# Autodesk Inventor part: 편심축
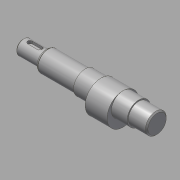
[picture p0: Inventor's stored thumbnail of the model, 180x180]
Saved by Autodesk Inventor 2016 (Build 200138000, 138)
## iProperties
Created: 2017-08
Part Number: 편심축
Material: 강철, 연강
Document SubType Name: Modeling
Designer: mduedu
Density: 1 g/cm^3
Appearance: 강철
Author: mduedu
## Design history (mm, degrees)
sketch "스케치1"
  geometry: L1 (0, 0)-(110, 0); L2 (110, 0)-(110, 8.5); L3 (110, 8.5)-(95, 8.5); L4 (95, 8.5)-(95, 9.5); L5 (95, 9.5)-(51, 9.5); L6 (51, 9.5)-(51, 8.5); L7 (51, 8.5)-(19, 8.5); L8 (19, 8.5)-(19, 6); L9 (19, 6)-(0, 6); L10 (0, 6)-(0, 0)
  constraints: 20 end point, 6 parallel, 2 collinear, 2 perpendicular, 1 horizontal
  dimensions: "d0" = 110 distance of L1.start L1.end; "d1" = 17 diameter of L3 L1; "d2" = 19 diameter of L5 L1; "d3" = 12 diameter of L9 L1; "d4" = 19 distance of L8.end L9.end; "d5" = 15 distance of L2.end L3.end; "d6" = 44 distance of L4.end L5.end
revolve "회전1" sketch "스케치1" stored, may be unused: angle "d7" = 90 deg
node "작업 평면1"
sketch "스케치2"
  geometry: C1 r 9.5 at (0, 0) reference; C2 r 13 at (0, -3.5); 1 further point
  constraints: 1 centre point, 1 tangent, 1 vertical alignment
  dimensions: "d8" = 3.5 distance of point (0, 0) C2.centre
extrude "돌출1" join sketch "스케치2" stored distance "d9" = 18; taper "d10" = 0 deg
chamfer "모따기1" distance "d11" = 1; stored, may be unused: second distance "d12" = 2, angle "d13" = 45 deg
node "작업 평면2"
sketch "스케치3"
  geometry: L1 (3.5, -2)-(-4.5, -2); L2 (-4.5, -2)-(-4.5, 2); L3 (-4.5, 2)-(3.5, 2); L4 (3.5, 2)-(3.5, -2); L5 (9.5, 6)-(9.5, -6) reference; A1 r 2 centre (3.5, 0) between (3.5, -2) and (3.5, 2); A2 r 2 centre (-4.5, 0) between (-4.5, 2) and (-4.5, -2); A3 r 2 centre (3.5, 0) between (3.5, 2) and (3.5, -2); A4 r 2 centre (-4.5, 0) between (-4.5, -2) and (-4.5, 2); 1 further point
  constraints: 8 end point, 8 point on circle, 4 centre point, 2 midpoint, 2 parallel, 1 horizontal, 1 horizontal alignment, 1 perpendicular
  dimensions: "d14" = 12 dimension on A2 A1; "d16" = 4 distance between parallel lines of L3 L1; "d17" = 4 distance edge to line of A1 L5
extrude "돌출2" cut sketch "스케치3" distance "d18" = 2.5; taper "d19" = 0 deg
chamfer "모따기2" distance "d20" = 1; stored, may be unused: second distance "d21" = 2, angle "d22" = 45 deg
chamfer "모따기3" distance "d23" = 1; stored, may be unused: second distance "d24" = 2, angle "d25" = 60 deg
fillet "모깎기1" dims "d26" = 0.5
hole "구멍1" diameter "d29" = 3.242; stored, may be unused: countersink angle "d33" = 90 deg, drill point angle "d35" = 118 deg; dims "d30" = 8, "d31" = 4, "d32" = 2, "d34" = 10, "d36" = 10, "d37" = 10
node "솔리드1"
node "절단 모서리 투영1"
